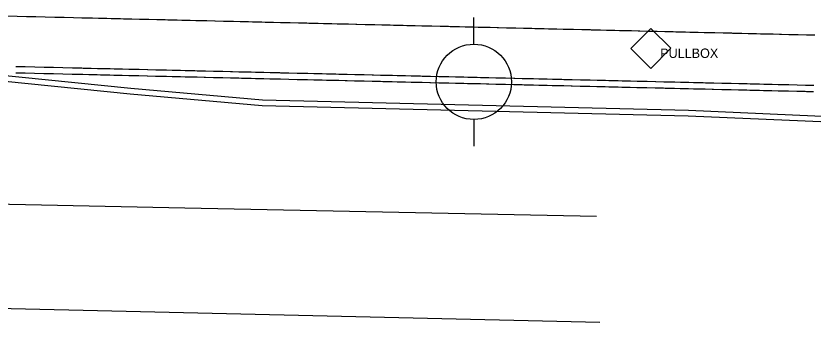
# Model space of a CAD drawing. Extents: x 2145380 to 2157287, y 139568 to 149130.
# Drawn here: x 2147421.2 to 2147505.9, y 143188.2 to 143220.7 of the extents above; entities that cross this region are included whole.
import ezdxf

# ---------------------------------------------------------------- set-up
doc = ezdxf.new("R2010")
doc.units = 0
for name, color, linetype in [('Default', 7, 'Continuous'), ('PR_PREVIOUSLY CONSTRUCTED', 7, 'Continuous'), ('TOPO_Curb Back', 7, 'Continuous'), ('TOPO_Misc Line', 7, 'Continuous'), ('TOPO_Power Pole', 7, 'Continuous'), ('TOPO_Power Pullbox', 7, 'Continuous')]:
    doc.layers.add(name, color=color, linetype=linetype)

# ---------------------------------------------------------------- blocks, each defined once
blk = doc.blocks.new('pulbox')
at = {"layer": 'Default'}
blk.add_lwpolyline([(-5.38, -0.01), (-0.02, 5.42), (5.4, 0.06), (0.05, -5.36), (-5.38, -0.01)], dxfattribs=at)
blk.add_text('PULLBOX', height=2.54, dxfattribs=at).set_placement((2.54, -2.54))
blk = doc.blocks.new('POWPOL')
at = {"layer": 'TOPO_Power Pole'}
for p, q in [((0, 10.16), (0, 17.34)), ((0, -10.16), (0, -17.34))]:
    blk.add_line(p, q, dxfattribs=at)
blk.add_circle((0, 0), 10.16, dxfattribs=at)

msp = doc.modelspace()

# ---------------------------------------------------------------- linework, layer by layer
at = {"layer": 'PR_PREVIOUSLY CONSTRUCTED'}
for points in [[(2147420.308, 143220.689), (2147421.308, 143220.665), (2147422.308, 143220.642), (2147423.308, 143220.618), (2147424.307, 143220.595), (2147425.307, 143220.571), (2147426.307, 143220.547), (2147427.306, 143220.524), (2147428.191, 143220.503), (2147428.306, 143220.5), (2147428.446, 143220.497), (2147429.076, 143220.482), (2147429.306, 143220.477), (2147429.961, 143220.461), (2147430.306, 143220.453), (2147430.845, 143220.441), (2147431.305, 143220.43), (2147431.73, 143220.42), (2147432.305, 143220.406), (2147432.615, 143220.399), (2147433.305, 143220.383), (2147433.499, 143220.378), (2147434.305, 143220.359), (2147434.384, 143220.357), (2147435.269, 143220.336), (2147435.304, 143220.336), (2147436.154, 143220.316), (2147436.304, 143220.312), (2147437.038, 143220.295), (2147437.304, 143220.288), (2147437.923, 143220.274), (2147438.303, 143220.265), (2147438.808, 143220.253), (2147439.303, 143220.241), (2147439.692, 143220.232), (2147440.303, 143220.218), (2147440.577, 143220.211), (2147441.303, 143220.194), (2147441.462, 143220.19), (2147442.302, 143220.171), (2147442.347, 143220.17), (2147443.231, 143220.149), (2147443.302, 143220.147), (2147444.116, 143220.128), (2147444.302, 143220.124), (2147445.001, 143220.107), (2147445.302, 143220.1), (2147445.885, 143220.086), (2147446.301, 143220.076), (2147446.77, 143220.065), (2147447.301, 143220.053), (2147447.655, 143220.045), (2147448.301, 143220.029), (2147448.54, 143220.024), (2147449.3, 143220.006), (2147449.424, 143220.003), (2147450.3, 143219.982), (2147450.309, 143219.982), (2147451.194, 143219.961), (2147451.3, 143219.959), (2147452.078, 143219.94), (2147452.3, 143219.935), (2147452.963, 143219.92), (2147453.299, 143219.912), (2147453.848, 143219.899), (2147454.299, 143219.888), (2147454.733, 143219.878), (2147455.299, 143219.865), (2147455.617, 143219.857), (2147456.298, 143219.841), (2147456.502, 143219.836), (2147457.298, 143219.817), (2147457.387, 143219.815), (2147458.271, 143219.795), (2147458.298, 143219.794), (2147459.156, 143219.774), (2147459.298, 143219.77), (2147460.041, 143219.753), (2147460.297, 143219.747), (2147460.925, 143219.732), (2147461.297, 143219.723), (2147461.81, 143219.711), (2147462.297, 143219.7), (2147462.695, 143219.69), (2147463.297, 143219.676), (2147463.58, 143219.669), (2147464.296, 143219.653), (2147464.464, 143219.649), (2147465.296, 143219.629), (2147465.349, 143219.628), (2147466.234, 143219.607), (2147466.296, 143219.605), (2147467.118, 143219.586), (2147467.295, 143219.582), (2147468.003, 143219.565), (2147468.295, 143219.558), (2147468.888, 143219.544), (2147469.295, 143219.535), (2147469.773, 143219.524), (2147470.295, 143219.511), (2147470.657, 143219.503), (2147471.294, 143219.488), (2147471.542, 143219.482), (2147472.294, 143219.464), (2147472.427, 143219.461), (2147473.294, 143219.441), (2147473.311, 143219.44), (2147474.196, 143219.419), (2147474.293, 143219.417), (2147475.081, 143219.399), (2147475.293, 143219.394), (2147475.966, 143219.378), (2147476.293, 143219.37), (2147476.85, 143219.357), (2147477.293, 143219.346), (2147477.735, 143219.336), (2147478.292, 143219.323), (2147478.62, 143219.315), (2147479.292, 143219.299), (2147479.504, 143219.294), (2147480.292, 143219.276), (2147480.389, 143219.273), (2147481.274, 143219.253), (2147481.292, 143219.252), (2147482.159, 143219.232), (2147482.291, 143219.229), (2147483.043, 143219.211), (2147483.291, 143219.205), (2147483.928, 143219.19), (2147484.291, 143219.182), (2147484.813, 143219.169), (2147485.29, 143219.158), (2147485.697, 143219.148), (2147486.29, 143219.134), (2147486.582, 143219.128), (2147487.29, 143219.111), (2147487.467, 143219.107), (2147488.29, 143219.087), (2147488.352, 143219.086), (2147489.236, 143219.065), (2147489.289, 143219.064), (2147490.121, 143219.044), (2147490.289, 143219.04), (2147490.429, 143219.037), (2147491.006, 143219.023), (2147491.289, 143219.017), (2147491.89, 143219.003), (2147492.288, 143218.993), (2147492.775, 143218.982), (2147493.288, 143218.97), (2147493.66, 143218.961), (2147494.288, 143218.946), (2147494.544, 143218.94), (2147495.288, 143218.923), (2147495.429, 143218.919), (2147496.287, 143218.899), (2147496.314, 143218.898), (2147497.199, 143218.878), (2147497.287, 143218.875), (2147498.083, 143218.857), (2147498.287, 143218.852), (2147498.968, 143218.836), (2147499.287, 143218.828), (2147499.853, 143218.815), (2147500.286, 143218.805), (2147500.737, 143218.794), (2147501.286, 143218.781), (2147501.622, 143218.773), (2147502.286, 143218.758), (2147502.507, 143218.752), (2147503.285, 143218.734), (2147503.392, 143218.732), (2147504.276, 143218.711), (2147504.285, 143218.711), (2147505.161, 143218.69), (2147505.285, 143218.687), (2147506.046, 143218.669)], [(2147421.182, 143215.327), (2147422.182, 143215.303), (2147423.182, 143215.28), (2147424.182, 143215.256), (2147425.181, 143215.233), (2147426.181, 143215.209), (2147427.181, 143215.185), (2147428.065, 143215.165), (2147428.18, 143215.162), (2147428.32, 143215.159), (2147428.95, 143215.144), (2147429.18, 143215.138), (2147429.835, 143215.123), (2147430.18, 143215.115), (2147430.72, 143215.102), (2147431.18, 143215.091), (2147431.604, 143215.081), (2147432.179, 143215.068), (2147432.489, 143215.06), (2147433.179, 143215.044), (2147433.374, 143215.04), (2147434.179, 143215.021), (2147434.258, 143215.019), (2147435.143, 143214.998), (2147435.179, 143214.997), (2147436.028, 143214.977), (2147436.178, 143214.973), (2147436.913, 143214.956), (2147437.178, 143214.95), (2147437.797, 143214.935), (2147438.178, 143214.926), (2147438.682, 143214.914), (2147439.177, 143214.903), (2147439.567, 143214.894), (2147440.177, 143214.879), (2147440.451, 143214.873), (2147441.177, 143214.856), (2147441.336, 143214.852), (2147442.177, 143214.832), (2147442.221, 143214.831), (2147443.106, 143214.81), (2147443.176, 143214.809), (2147443.99, 143214.789), (2147444.176, 143214.785), (2147444.875, 143214.769), (2147445.176, 143214.762), (2147445.76, 143214.748), (2147446.175, 143214.738), (2147446.644, 143214.727), (2147447.175, 143214.714), (2147447.529, 143214.706), (2147448.175, 143214.691), (2147448.414, 143214.685), (2147449.175, 143214.667), (2147449.298, 143214.664), (2147450.174, 143214.644), (2147450.183, 143214.644), (2147451.068, 143214.623), (2147451.174, 143214.62), (2147451.953, 143214.602), (2147452.174, 143214.597), (2147452.837, 143214.581), (2147453.174, 143214.573), (2147453.722, 143214.56), (2147454.173, 143214.55), (2147454.607, 143214.539), (2147455.173, 143214.526), (2147455.491, 143214.519), (2147456.173, 143214.502), (2147456.376, 143214.498), (2147457.172, 143214.479), (2147457.261, 143214.477), (2147458.146, 143214.456), (2147458.172, 143214.455), (2147459.03, 143214.435), (2147459.172, 143214.432), (2147459.915, 143214.414), (2147460.172, 143214.408), (2147460.8, 143214.393), (2147461.171, 143214.385), (2147461.684, 143214.373), (2147462.171, 143214.361), (2147462.569, 143214.352), (2147463.171, 143214.338), (2147463.454, 143214.331), (2147464.17, 143214.314), (2147464.339, 143214.31), (2147465.17, 143214.291), (2147465.223, 143214.289), (2147466.108, 143214.268), (2147466.17, 143214.267), (2147466.993, 143214.248), (2147467.17, 143214.243), (2147467.877, 143214.227), (2147468.169, 143214.22), (2147468.762, 143214.206), (2147469.169, 143214.196), (2147469.647, 143214.185), (2147470.169, 143214.173), (2147470.532, 143214.164), (2147471.169, 143214.149), (2147471.416, 143214.143), (2147472.168, 143214.126), (2147472.301, 143214.123), (2147473.168, 143214.102), (2147473.186, 143214.102), (2147474.07, 143214.081), (2147474.168, 143214.079), (2147474.955, 143214.06), (2147475.167, 143214.055), (2147475.84, 143214.039), (2147476.167, 143214.031), (2147476.725, 143214.018), (2147477.167, 143214.008), (2147477.609, 143213.997), (2147478.167, 143213.984), (2147478.494, 143213.977), (2147479.166, 143213.961), (2147479.379, 143213.956), (2147480.166, 143213.937), (2147480.263, 143213.935), (2147481.148, 143213.914), (2147481.166, 143213.914), (2147482.033, 143213.893), (2147482.165, 143213.89), (2147482.917, 143213.872), (2147483.165, 143213.867), (2147483.802, 143213.852), (2147484.165, 143213.843), (2147484.687, 143213.831), (2147485.165, 143213.82), (2147485.572, 143213.81), (2147486.164, 143213.796), (2147486.456, 143213.789), (2147487.164, 143213.772), (2147487.341, 143213.768), (2147488.164, 143213.749), (2147488.226, 143213.747), (2147489.11, 143213.727), (2147489.164, 143213.725), (2147489.995, 143213.706), (2147490.163, 143213.702), (2147490.303, 143213.698), (2147490.88, 143213.685), (2147491.163, 143213.678), (2147491.765, 143213.664), (2147492.163, 143213.655), (2147492.649, 143213.643), (2147493.162, 143213.631), (2147493.534, 143213.622), (2147494.162, 143213.608), (2147494.419, 143213.602), (2147495.162, 143213.584), (2147495.303, 143213.581), (2147496.162, 143213.56), (2147496.188, 143213.56), (2147497.073, 143213.539), (2147497.161, 143213.537), (2147497.958, 143213.518), (2147498.161, 143213.513), (2147498.842, 143213.497), (2147499.161, 143213.49), (2147499.727, 143213.476), (2147500.16, 143213.466), (2147500.612, 143213.456), (2147501.16, 143213.443), (2147501.496, 143213.435), (2147502.16, 143213.419), (2147502.381, 143213.414), (2147503.16, 143213.396), (2147503.266, 143213.393), (2147504.151, 143213.372), (2147504.159, 143213.372), (2147505.035, 143213.351), (2147505.159, 143213.349), (2147505.92, 143213.331)], [(2147421.167, 143214.659), (2147422.166, 143214.636), (2147423.166, 143214.612), (2147424.166, 143214.589), (2147425.166, 143214.565), (2147426.165, 143214.541), (2147427.165, 143214.518), (2147428.05, 143214.497), (2147428.165, 143214.494), (2147428.305, 143214.491), (2147428.934, 143214.476), (2147429.164, 143214.471), (2147429.819, 143214.455), (2147430.164, 143214.447), (2147430.704, 143214.435), (2147431.164, 143214.424), (2147431.589, 143214.414), (2147432.164, 143214.4), (2147432.473, 143214.393), (2147433.163, 143214.377), (2147433.358, 143214.372), (2147434.163, 143214.353), (2147434.243, 143214.351), (2147435.127, 143214.33), (2147435.163, 143214.33), (2147436.012, 143214.31), (2147436.163, 143214.306), (2147436.897, 143214.289), (2147437.162, 143214.282), (2147437.782, 143214.268), (2147438.162, 143214.259), (2147438.666, 143214.247), (2147439.162, 143214.235), (2147439.551, 143214.226), (2147440.161, 143214.212), (2147440.436, 143214.205), (2147441.161, 143214.188), (2147441.32, 143214.184), (2147442.161, 143214.165), (2147442.205, 143214.164), (2147443.09, 143214.143), (2147443.161, 143214.141), (2147443.975, 143214.122), (2147444.16, 143214.118), (2147444.859, 143214.101), (2147445.16, 143214.094), (2147445.744, 143214.08), (2147446.16, 143214.07), (2147446.629, 143214.059), (2147447.159, 143214.047), (2147447.513, 143214.039), (2147448.159, 143214.023), (2147448.398, 143214.018), (2147449.159, 143214), (2147449.283, 143213.997), (2147450.159, 143213.976), (2147450.167, 143213.976), (2147451.052, 143213.955), (2147451.158, 143213.953), (2147451.937, 143213.934), (2147452.158, 143213.929), (2147452.822, 143213.914), (2147453.158, 143213.906), (2147453.706, 143213.893), (2147454.158, 143213.882), (2147454.591, 143213.872), (2147455.157, 143213.859), (2147455.476, 143213.851), (2147456.157, 143213.835), (2147456.36, 143213.83), (2147457.157, 143213.811), (2147457.245, 143213.809), (2147458.13, 143213.789), (2147458.156, 143213.788), (2147459.015, 143213.768), (2147459.156, 143213.764), (2147459.899, 143213.747), (2147460.156, 143213.741), (2147460.784, 143213.726), (2147461.156, 143213.717), (2147461.669, 143213.705), (2147462.155, 143213.694), (2147462.553, 143213.684), (2147463.155, 143213.67), (2147463.438, 143213.663), (2147464.155, 143213.647), (2147464.323, 143213.643), (2147465.154, 143213.623), (2147465.208, 143213.622), (2147466.092, 143213.601), (2147466.154, 143213.599), (2147466.977, 143213.58), (2147467.154, 143213.576), (2147467.862, 143213.559), (2147468.154, 143213.552), (2147468.746, 143213.538), (2147469.153, 143213.529), (2147469.631, 143213.518), (2147470.153, 143213.505), (2147470.516, 143213.497), (2147471.153, 143213.482), (2147471.401, 143213.476), (2147472.153, 143213.458), (2147472.285, 143213.455), (2147473.152, 143213.435), (2147473.17, 143213.434), (2147474.055, 143213.413), (2147474.152, 143213.411), (2147474.939, 143213.393), (2147475.152, 143213.388), (2147475.824, 143213.372), (2147476.151, 143213.364), (2147476.709, 143213.351), (2147477.151, 143213.34), (2147477.594, 143213.33), (2147478.151, 143213.317), (2147478.478, 143213.309), (2147479.151, 143213.293), (2147479.363, 143213.288), (2147480.15, 143213.27), (2147480.248, 143213.267), (2147481.132, 143213.247), (2147481.15, 143213.246), (2147482.017, 143213.226), (2147482.15, 143213.223), (2147482.902, 143213.205), (2147483.149, 143213.199), (2147483.786, 143213.184), (2147484.149, 143213.176), (2147484.671, 143213.163), (2147485.149, 143213.152), (2147485.556, 143213.142), (2147486.149, 143213.128), (2147486.441, 143213.122), (2147487.148, 143213.105), (2147487.325, 143213.101), (2147488.148, 143213.081), (2147488.21, 143213.08), (2147489.095, 143213.059), (2147489.148, 143213.058), (2147489.979, 143213.038), (2147490.148, 143213.034), (2147490.288, 143213.031), (2147490.864, 143213.017), (2147491.147, 143213.011), (2147491.749, 143212.997), (2147492.147, 143212.987), (2147492.634, 143212.976), (2147493.147, 143212.964), (2147493.518, 143212.955), (2147494.146, 143212.94), (2147494.403, 143212.934), (2147495.146, 143212.917), (2147495.288, 143212.913), (2147496.146, 143212.893), (2147496.172, 143212.892), (2147497.057, 143212.872), (2147497.146, 143212.869), (2147497.942, 143212.851), (2147498.145, 143212.846), (2147498.827, 143212.83), (2147499.145, 143212.822), (2147499.711, 143212.809), (2147500.145, 143212.799), (2147500.596, 143212.788), (2147501.144, 143212.775), (2147501.481, 143212.767), (2147502.144, 143212.752), (2147502.365, 143212.746), (2147503.144, 143212.728), (2147503.25, 143212.726), (2147504.135, 143212.705), (2147504.144, 143212.705), (2147505.02, 143212.684), (2147505.143, 143212.681), (2147505.904, 143212.663)]]:
    msp.add_lwpolyline(points, dxfattribs=at)
at = {"layer": 'TOPO_Curb Back'}
for points in [[(2147377.31, 143217.58), (2147403.563, 143215.419), (2147433.326, 143212.43), (2147447.34, 143211.18), (2147492.585, 143210.09), (2147509.145, 143209.355)], [(2147377.359, 143218.178), (2147403.618, 143216.016), (2147433.382, 143213.027), (2147447.374, 143211.779), (2147492.605, 143210.689), (2147509.176, 143209.955)]]:
    msp.add_lwpolyline(points, dxfattribs=at)
at = {"layer": 'TOPO_Misc Line'}
for points in [[(2147386.618, 143201.423), (2147439.118, 143200.301), (2147482.851, 143199.426)], [(2147387.907, 143190.266), (2147414.568, 143189.752), (2147483.201, 143188.179)]]:
    msp.add_lwpolyline(points, dxfattribs=at)

# ---------------------------------------------------------------- block references
at = {"layer": 'TOPO_Power Pole', "xscale": 0.39370000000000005, "yscale": 0.3937000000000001}
msp.add_blockref('POWPOL', (2147469.823, 143213.691), dxfattribs=at)
at = {"layer": 'TOPO_Power Pullbox', "xscale": 0.39370000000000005, "yscale": 0.3937000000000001}
msp.add_blockref('pulbox', (2147488.613, 143217.229), dxfattribs=at)

doc.saveas('drawing.dxf')
